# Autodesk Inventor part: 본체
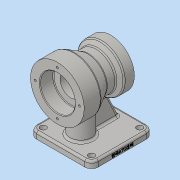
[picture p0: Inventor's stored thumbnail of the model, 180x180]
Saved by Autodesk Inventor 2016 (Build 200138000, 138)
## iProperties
Created: 2019-01
Part Number: 본체
Material: Generic
Document SubType Name: Modeling
Designer: Administrator
Density: 1 g/cm^3
Appearance: Default
Mass: 332.895 g
Surface Area: 600.964 cm^2
Volume: 332.895 cm^3
Author: Administrator
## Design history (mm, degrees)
sketch "스케치1"
  geometry: L1 (46, -46)-(-46, -46); L2 (-46, -46)-(-46, 46); L3 (-46, 46)-(46, 46); L4 (46, 46)-(46, -46); L5 (46, -46)-(-46, 46); L6 (-46, -46)-(46, 46); 1 further point
  constraints: 12 end point, 2 midpoint, 2 parallel, 1 horizontal, 1 perpendicular
  dimensions: "d0" = 92 distance of L2.end L3.end; "d1" = 92 distance of L1.end L2.end
extrude "돌출1" new body sketch "스케치1" distance "d2" = 10; taper "d3" = 0 deg
sketch "스케치2"
  geometry: L1 (-51, 80)-(29, 80); L2 (46, 0)-(-46, 0) reference; L3 (-46, 10)-(46, 10) reference; L4 (-46, 10)-(-51, 80); L5 (-51, 80)-(-51, 120); L6 (-51, 120)-(-26, 120); L7 (-26, 120)-(-5.215, 108); L8 (-5.215, 108)-(8.126, 108); L9 (8.126, 108)-(14, 115); L10 (14, 115)-(29, 115); L11 (29, 115)-(29, 80); 1 further point
  constraints: 18 end point, 2 parallel, 2 perpendicular, 1 horizontal, 1 vertical, 1 vertical alignment
  dimensions: "d4" = 80 distance of L1.start L1.end; "d5" = 80 distance between parallel lines of L2 L1; "d6" = 5 horizontal distance of L2.end L1.start; "d7" = 25 distance of L5.end L6.end; "d8" = 15 distance of L9.end L10.end; "d10" = 30 deg angle of L8 L7; "d11" = 50 deg angle of L9 L8; "d12" = 80 diameter of L6 L1; "d13" = 70 diameter of L10 L1; "d14" = 56 diameter of L8 L1
revolve "회전1" sketch "스케치2" stored, may be unused: angle "d15" = 90 deg
sketch "스케치3"
  geometry: L1 (46, -46)-(-46, -46) reference; L2 (-46, -46)-(-46, 46) reference; C1 r 16 at (0, -16); 1 further point
  constraints: 1 centre point
  dimensions: "d16" = 16 radius of C1; "d17" = 30 distance from line of L1 C1.centre; "d18" = 46 distance from line of L2 C1.centre
extrude "돌출2" join sketch "스케치3" stored distance "d19" = 10; taper "d20" = 0 deg
sketch "스케치4"
  geometry: L1 (46, 10)-(-46, 10) reference; L2 (36, 10)-(19.679, 45); L3 (14, 45)-(29, 45) reference; L4 (46, 0)-(46, 10) reference; 1 further point
  constraints: 2 end point, 2 point on line
  dimensions: "d21" = 25 deg angle of L4 L2; "d22" = 10 distance from line of L4 L2.start
feature "리브1" sketch "스케치4" dims "d23" = 1, "d24" = 10, "d25" = 0, "d26" = 0, "d27" = 1, "d28" = 1
sketch "스케치5"
  geometry: L1 (-51, 40)-(-51, 120) reference; L2 (-51, 80)-(29, 80); L3 (29, 45)-(29, 115) reference; L4 (-51, 106)-(-31, 106); L5 (-31, 106)-(-31, 96); L6 (-31, 96)-(12, 96); L7 (12, 96)-(12, 100); L8 (12, 100)-(29, 100); 1 further point
  constraints: 12 end point, 4 perpendicular, 2 midpoint, 2 point on line, 1 horizontal
  dimensions: "d29" = 52 diameter of L4 L2; "d30" = 40 diameter of L8 L2; "d31" = 32 diameter of L6 L2; "d32" = 20 distance of L4.start L4.end; "d33" = 17 distance of L7.end L8.end
revolve "회전2" sketch "스케치5" stored, may be unused: angle "d34" = 90 deg
sketch "스케치6"
  geometry: C1 r 16 at (0, 0) reference; 2 further points
  constraints: 1 vertical alignment
  dimensions: "d35" = 33 distance of C1.centre point (0, 33)
hole "구멍1" sketch "스케치6" at (0, 33) diameter "d36" = 3.242; stored, may be unused: countersink angle "d40" = 90 deg, drill point angle "d42" = 118 deg; dims "d37" = 9, "d38" = 4, "d39" = 2, "d41" = 11
sketch "스케치7"
  geometry: C1 r 16 at (0, 0) reference; 2 further points
  constraints: 1 vertical alignment
  dimensions: "d46" = 27.5 distance of C1.centre point (0, -27.5)
hole "구멍2" sketch "스케치7" at (0, -27.5) diameter "d47" = 3.242; stored, may be unused: countersink angle "d51" = 90 deg, drill point angle "d53" = 118 deg; dims "d48" = 9, "d49" = 4, "d50" = 2, "d52" = 11
fillet "모깎기1" dims "d57" = 10
hole "구멍3" diameter "d60" = 9; stored, may be unused: countersink angle "d64" = 90 deg, drill point angle "d66" = 118 deg; dims "d58" = 10, "d59" = 10, "d61" = 9, "d62" = 4, "d63" = 2, "d65" = 11
hole "구멍4" diameter "d69" = 9; stored, may be unused: countersink angle "d73" = 90 deg, drill point angle "d75" = 118 deg; dims "d67" = 10, "d68" = 10, "d70" = 9, "d71" = 4, "d72" = 2, "d74" = 11
hole "구멍5" diameter "d78" = 9; stored, may be unused: countersink angle "d82" = 90 deg, drill point angle "d84" = 118 deg; dims "d76" = 10, "d77" = 10, "d79" = 9, "d80" = 4, "d81" = 2, "d83" = 11
hole "구멍6" diameter "d87" = 9; stored, may be unused: countersink angle "d91" = 90 deg, drill point angle "d93" = 118 deg; dims "d85" = 10, "d86" = 10, "d88" = 9, "d89" = 4, "d90" = 2, "d92" = 11
sketch "스케치8"
  geometry: L1 (0, 82)-(0, 72) reference; L2 (-10, -10)-(0, -10) reference; 2 further points
  constraints: 1 other
  dimensions: "d94" = 4 distance from line of L1 point (-4, 36); "d95" = 46 distance from line of L2 point (-4, 36)
feature "엠보싱1" sketch "스케치8" dims "d0" = 92, "d1" = 92, "d4" = 80, "d5" = 80, "d6" = 5, "d7" = 25, "d8" = 15, "d10" = 30 deg, "d11" = 50 deg, "d12" = 80, "d13" = 70, "d14" = 56, "d96" = 0.5, "d97" = 0
fillet "모깎기2" dims "d98" = 1, "d99" = 0.6
chamfer "모따기1" distance "d100" = 1; stored, may be unused: second distance "d101" = 2, angle "d102" = 45 deg
fillet "모깎기3" dims "d103" = 3
fillet "모깎기4" dims "d104" = 3
fillet "모깎기5" dims "d105" = 3
fillet "모깎기6" dims "d106" = 3
feature "분할1"
node "솔리드1"
pattern_circular "원형 패턴1" dims angle "d44" = 360 deg
pattern_circular "원형 패턴2" dims angle "d55" = 360 deg
